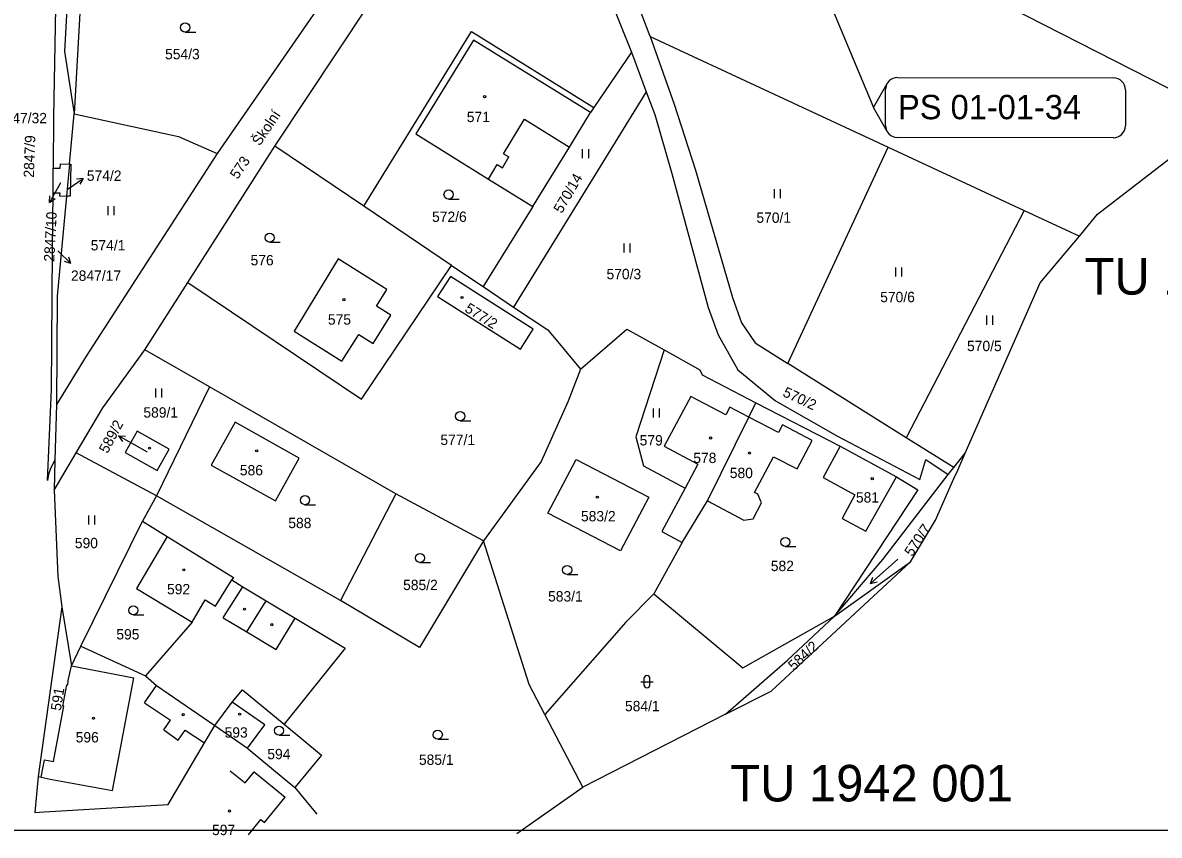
# Model space of a CAD drawing. Extents: x -558358 to -557517, y -1073785 to -1073189.
# Drawn here: x -558184.5 to -557998, y -1073784.9 to -1073651.5 of the extents above; entities that cross this region are included whole.
import ezdxf

# ---------------------------------------------------------------- set-up
doc = ezdxf.new("R2010")
doc.units = 0
for name, color, linetype in [('Hranice parcel', 7, 'Continuous'), ('Parcelní čísla', 7, 'Continuous'), ('Pop  PČ popisy', 7, 'Continuous'), ('Vnitřní kresba', 7, 'Continuous'), ('Vrstva 1', 7, 'Continuous'), ('Vrstva 2', 7, 'Continuous'), ('Vrstva 28', 7, 'Continuous'), ('Značky budov', 7, 'Continuous'), ('Značky kultur', 7, 'Continuous')]:
    doc.layers.add(name, color=color, linetype=linetype)

msp = doc.modelspace()

# ---------------------------------------------------------------- linework, layer by layer
at = {"layer": 'Hranice parcel'}
for p, q in [((-558126.57, -1073635.37), (-558152.59, -1073672.96)), ((-558047.53, -1073636.2), (-557987.38, -1073666.93)), ((-558083.83, -1073647.78), (-558081.75, -1073653.27)), ((-558081.75, -1073653.27), (-558081.56, -1073653.8)), ((-558081.56, -1073653.8), (-558042.48, -1073671.96)), ((-558084.61, -1073656.37), (-558090.78, -1073665.45)), ((-558084.61, -1073656.37), (-558082.19, -1073662.86)), ((-558082.19, -1073662.86), (-558103.95, -1073698.19)), ((-558082.19, -1073662.86), (-558080.79, -1073666.61)), ((-558090.78, -1073665.45), (-558091.34, -1073666.27)), ((-558176.83, -1073674.75), (-558176.05, -1073666.5)), ((-558008.13, -1073682.96), (-557987.38, -1073666.93)), ((-558157.39, -1073694.14), (-558143.16, -1073671.79)), ((-558128.54, -1073681.64), (-558143.16, -1073671.79)), ((-558058.98, -1073707.44), (-558042.48, -1073671.96)), ((-558042.48, -1073671.96), (-558020.18, -1073682.32)), ((-558178.3, -1073674.68), (-558176.83, -1073674.75)), ((-558176.83, -1073674.75), (-558177.33, -1073679.98)), ((-558176.83, -1073674.75), (-558176.6, -1073674.76)), ((-558176.6, -1073674.76), (-558176.71, -1073680)), ((-558179.54, -1073679.43), (-558179.49, -1073675.4)), ((-558178.45, -1073679.93), (-558177.33, -1073679.98)), ((-558176.71, -1073680), (-558177.33, -1073679.98)), ((-558114.13, -1073691.34), (-558128.54, -1073681.64)), ((-558100.81, -1073681.69), (-558108.93, -1073694.83)), ((-558020.18, -1073682.32), (-558039.55, -1073719.63)), ((-558020.18, -1073682.32), (-558011.11, -1073686.54)), ((-558011.11, -1073686.54), (-558008.13, -1073682.96)), ((-558017.53, -1073694.23), (-558011.11, -1073686.54)), ((-558114.13, -1073691.34), (-558108.93, -1073694.83)), ((-558164.46, -1073705.23), (-558157.39, -1073694.14)), ((-558108.93, -1073694.83), (-558103.95, -1073698.19)), ((-558029.85, -1073722.15), (-558017.53, -1073694.23)), ((-558153.86, -1073711.3), (-558164.46, -1073705.23)), ((-558079.26, -1073705.23), (-558083.89, -1073719.49)), ((-558039.55, -1073719.63), (-558058.98, -1073707.44)), ((-558153.86, -1073711.3), (-558162.58, -1073729.18)), ((-558123.29, -1073728.86), (-558153.86, -1073711.3)), ((-558178.98, -1073714.16), (-558179.23, -1073723.31)), ((-558065.38, -1073716.24), (-558064.19, -1073713.89)), ((-558064.19, -1073713.89), (-558050.38, -1073721.04)), ((-558072.16, -1073729.98), (-558065.38, -1073716.24)), ((-558083.89, -1073719.49), (-558082.62, -1073724.25)), ((-558031.72, -1073724.54), (-558039.55, -1073719.63)), ((-558050.38, -1073721.04), (-558041.12, -1073726.03)), ((-558179.37, -1073728.25), (-558175.74, -1073722.09)), ((-558179.23, -1073723.31), (-558179.37, -1073728.25)), ((-558162.58, -1073729.18), (-558175.74, -1073722.09)), ((-558031.72, -1073724.54), (-558029.85, -1073722.15)), ((-558082.62, -1073724.25), (-558075.83, -1073727.93)), ((-558032.62, -1073725.69), (-558031.72, -1073724.54)), ((-558162.58, -1073729.18), (-558164.87, -1073733.32)), ((-558132.34, -1073746.32), (-558162.58, -1073729.18)), ((-558123.29, -1073728.86), (-558132.34, -1073746.32)), ((-558108.92, -1073736.57), (-558123.29, -1073728.86)), ((-558076.28, -1073736.83), (-558072.16, -1073729.98)), ((-558174.95, -1073753.84), (-558164.87, -1073733.32)), ((-558164.87, -1073733.32), (-558160.79, -1073735.84)), ((-558076.28, -1073736.83), (-558080.95, -1073745.27)), ((-558061.7, -1073761.21), (-558038.85, -1073740)), ((-558051.32, -1073748.93), (-558043.37, -1073739.61)), ((-558051.32, -1073748.93), (-558038.85, -1073740)), ((-558080.95, -1073745.27), (-558085.52, -1073749.88)), ((-558178.08, -1073747.39), (-558181.97, -1073775.25)), ((-558178.08, -1073747.39), (-558176.52, -1073757.07)), ((-558058.99, -1073756.15), (-558051.32, -1073748.93)), ((-558085.52, -1073749.88), (-558098.82, -1073765.08)), ((-558176.52, -1073757.07), (-558174.95, -1073753.84)), ((-558174.95, -1073753.84), (-558164.36, -1073758.7)), ((-558069.16, -1073765.01), (-558058.99, -1073756.15)), ((-558069.16, -1073765.01), (-558061.7, -1073761.21)), ((-558152.96, -1073766.88), (-558150.14, -1073763.05)), ((-558092.62, -1073776.97), (-558098.82, -1073765.08)), ((-558069.16, -1073765.01), (-558092.62, -1073776.97)), ((-558152.96, -1073766.88), (-558147.64, -1073770.59)), ((-558147.64, -1073770.59), (-558147.54, -1073770.67)), ((-558147.54, -1073770.67), (-558139.85, -1073777.06)), ((-558181.97, -1073775.25), (-558182.51, -1073781.13)), ((-558139.85, -1073777.06), (-558136.25, -1073781.43)), ((-558103.4, -1073784.58), (-558092.62, -1073776.97)), ((-558182.51, -1073781.13), (-558181.01, -1073781.05))]:
    msp.add_line(p, q, dxfattribs=at)
for points in [[(-558086.19, -1073392.25), (-558100.56, -1073410.01), (-558117.51, -1073431.08), (-558131.78, -1073449.27), (-558138.48, -1073457.68), (-558143.38, -1073464.02), (-558146.99, -1073468.89), (-558150.46, -1073473.83), (-558152.02, -1073476.41), (-558154.26, -1073480.97), (-558156.46, -1073486.6), (-558158.91, -1073494.31), (-558160.3, -1073500.48), (-558162.16, -1073510.4), (-558165.76, -1073536.46), (-558169.94, -1073565.43), (-558173.74, -1073591.61), (-558177.66, -1073620.33), (-558178.51, -1073631.87), (-558179.02, -1073643), (-558179.24, -1073655.12), (-558179.45, -1073666.94), (-558179.49, -1073675.4)], [(-558175.82, -1073622.18), (-558177.63, -1073656.22), (-558176.05, -1073666.5)], [(-558175.82, -1073622.18), (-558174.18, -1073632.38), (-558176.05, -1073666.5)], [(-558143.16, -1073671.79), (-558122.68, -1073640.91), (-558116.74, -1073631.82), (-558110.18, -1073623.69)], [(-558110.18, -1073623.69), (-558095.16, -1073631.27), (-558088.2, -1073647.35), (-558084.61, -1073656.37)], [(-558128.54, -1073681.64), (-558110.84, -1073652.98), (-558090.78, -1073665.45)], [(-558091.34, -1073666.27), (-558110.52, -1073654.36), (-558120.01, -1073669.73), (-558108.1, -1073677.21), (-558100.81, -1073681.69)], [(-558081.56, -1073653.8), (-558077.6, -1073664.88), (-558074.09, -1073675.7), (-558068.03, -1073696.59), (-558066.56, -1073700.76), (-558064.34, -1073704.08), (-558058.98, -1073707.44)], [(-558176.05, -1073666.5), (-558158.95, -1073670.2), (-558152.59, -1073672.96)], [(-558100.81, -1073681.69), (-558094.8, -1073671.95), (-558091.34, -1073666.27)], [(-558080.79, -1073666.61), (-558077.98, -1073676.29), (-558072.03, -1073698.27), (-558070.37, -1073702.74), (-558067.15, -1073708.5), (-558060.97, -1073713.55), (-558050.8, -1073719.38), (-558037.27, -1073726.47), (-558036.33, -1073723.21), (-558032.62, -1073725.69)], [(-558152.59, -1073672.96), (-558174.12, -1073706.25), (-558178.98, -1073714.16)], [(-558179.49, -1073675.4), (-558178.35, -1073675.4), (-558178.3, -1073674.68)], [(-558180.47, -1073726.64), (-558179.79, -1073711.73), (-558179.61, -1073688.81), (-558179.54, -1073679.43)], [(-558179.54, -1073679.43), (-558178.44, -1073679.44), (-558178.45, -1073679.93)], [(-558177.33, -1073679.98), (-558178.88, -1073696.38), (-558178.98, -1073714.16)], [(-558157.39, -1073694.14), (-558128.92, -1073713.32), (-558114.13, -1073691.34)], [(-558124.75, -1073695.3), (-558132.74, -1073690.28), (-558139.98, -1073702.13), (-558132.13, -1073707.05), (-558129.35, -1073702.69), (-558127, -1073704.15), (-558124.1, -1073699.49), (-558126.45, -1073698.03), (-558124.75, -1073695.3)], [(-558114.32, -1073693.16), (-558116.42, -1073696.46), (-558102.81, -1073705.11), (-558100.72, -1073701.82), (-558114.32, -1073693.16)], [(-558103.95, -1073698.19), (-558098.36, -1073701.95), (-558092.97, -1073708.36)], [(-558092.97, -1073708.36), (-558085.4, -1073701.82), (-558079.26, -1073705.23)], [(-558175.74, -1073722.09), (-558171.39, -1073714.72), (-558164.46, -1073705.23)], [(-558079.26, -1073705.23), (-558073.37, -1073708.51), (-558073.01, -1073709.33), (-558064.19, -1073713.89)], [(-558092.97, -1073708.36), (-558095.02, -1073713.61), (-558099.46, -1073723.54), (-558108.92, -1073736.57)], [(-558065.38, -1073716.24), (-558068.48, -1073714.62), (-558069.13, -1073715.86), (-558074.89, -1073712.87), (-558079.25, -1073721.04), (-558073.73, -1073723.99), (-558075.83, -1073727.93)], [(-558072.16, -1073729.98), (-558066.15, -1073733.15), (-558064.66, -1073732.92), (-558063.26, -1073730.33), (-558063.88, -1073728.9), (-558064.4, -1073728.63), (-558061.31, -1073722.78), (-558057.44, -1073724.76), (-558054.98, -1073720.06), (-558059.84, -1073717.49), (-558060.51, -1073718.77), (-558065.38, -1073716.24)], [(-558139.17, -1073722.99), (-558149.67, -1073717.07), (-558153.56, -1073724.14), (-558143.05, -1073729.97), (-558139.17, -1073722.99)], [(-558160.49, -1073721.53), (-558165.71, -1073718.57), (-558167.69, -1073722.06), (-558162.47, -1073725.03), (-558160.49, -1073721.53)], [(-558050.38, -1073721.04), (-558053.17, -1073726.18), (-558047.96, -1073729.01), (-558050.05, -1073732.86), (-558046.14, -1073734.98), (-558041.12, -1073726.03)], [(-558179.23, -1073723.31), (-558179.97, -1073724.66), (-558180.29, -1073725.65), (-558180.47, -1073726.64)], [(-558081.79, -1073729.39), (-558086.39, -1073738.22), (-558098.32, -1073732.01), (-558093.7, -1073723.21), (-558081.79, -1073729.39)], [(-558031.69, -1073726.31), (-558031.08, -1073724.94), (-558029.85, -1073722.15)], [(-558041.12, -1073726.03), (-558037.61, -1073728.19), (-558051.32, -1073748.93)], [(-558043.37, -1073739.61), (-558035.2, -1073729), (-558032.62, -1073725.69)], [(-558038.85, -1073740), (-558034.7, -1073733.14), (-558031.69, -1073726.31)], [(-558179.37, -1073728.25), (-558178.74, -1073742.4), (-558178.08, -1073747.39)], [(-558075.83, -1073727.93), (-558079.61, -1073735.04), (-558076.28, -1073736.83)], [(-558160.79, -1073735.84), (-558165.86, -1073744.39), (-558156.72, -1073749.9), (-558164.36, -1073758.7)], [(-558160.79, -1073735.84), (-558149.94, -1073742.55), (-558150.18, -1073742.93), (-558148.38, -1073744.09), (-558144.55, -1073746.39), (-558139.78, -1073749.25), (-558131.58, -1073754.18), (-558141.63, -1073766.63)], [(-558108.92, -1073736.57), (-558119.39, -1073754.05), (-558132.34, -1073746.32)], [(-558098.82, -1073765.08), (-558101.41, -1073760.13), (-558108.92, -1073736.57)], [(-558080.95, -1073745.27), (-558066.32, -1073757.38), (-558051.32, -1073748.93)], [(-558181.97, -1073775.25), (-558181.48, -1073775.34), (-558180.95, -1073772.5), (-558179.48, -1073772.78), (-558177.77, -1073763.68), (-558177.92, -1073763.66), (-558177.27, -1073760.18), (-558177.12, -1073760.21), (-558177.05, -1073759.47), (-558176.52, -1073757.07)], [(-558164.36, -1073758.7), (-558162.58, -1073760.28), (-558152.96, -1073766.88)], [(-558150.14, -1073763.05), (-558148.43, -1073760.98), (-558141.63, -1073766.63)], [(-558147.64, -1073770.59), (-558144.77, -1073766.75), (-558150.14, -1073763.05)], [(-558181.01, -1073781.05), (-558160.65, -1073779.83), (-558154.69, -1073769.71), (-558152.96, -1073766.88)], [(-558141.63, -1073766.63), (-558135.48, -1073771.74), (-558139.85, -1073777.06)]]:
    msp.add_lwpolyline(points, dxfattribs=at)
at = {"layer": 'Pop  PČ popisy'}
for p, q in [((-558177.05, -1073678.78), (-558174.59, -1073677.06)), ((-558174.59, -1073677.06), (-558175.7, -1073677.22)), ((-558174.59, -1073677.06), (-558175.12, -1073678.04)), ((-558178.66, -1073678.4), (-558180.11, -1073681.02)), ((-558178.32, -1073677.78), (-558178.66, -1073678.4)), ((-558180.11, -1073681.02), (-558180.07, -1073679.91)), ((-558180.11, -1073681.02), (-558179.19, -1073680.39)), ((-558178.75, -1073688.95), (-558176.59, -1073691.03)), ((-558176.59, -1073691.03), (-558176.96, -1073689.98)), ((-558176.59, -1073691.03), (-558177.66, -1073690.7)), ((-558166.16, -1073720.8), (-558168.79, -1073719.34)), ((-558168.79, -1073719.34), (-558167.67, -1073719.39)), ((-558168.79, -1073719.34), (-558168.15, -1073720.27)), ((-558164.05, -1073721.99), (-558166.16, -1073720.8))]:
    msp.add_line(p, q, dxfattribs=at)
at = {"layer": 'Vnitřní kresba'}
for p, q in [((-558105.6, -1073673.04), (-558102.19, -1073667.36)), ((-558102.19, -1073667.36), (-558094.8, -1073671.95)), ((-558105.6, -1073673.04), (-558104.74, -1073673.55)), ((-558108.1, -1073677.21), (-558106.65, -1073674.8)), ((-558106.65, -1073674.8), (-558105.79, -1073675.32)), ((-558105.79, -1073675.32), (-558104.74, -1073673.55)), ((-558152.86, -1073747.27), (-558150.18, -1073742.93)), ((-558151.46, -1073748.94), (-558148.38, -1073744.09)), ((-558156.72, -1073749.9), (-558154.56, -1073746.22)), ((-558154.56, -1073746.22), (-558152.86, -1073747.27)), ((-558147.74, -1073751.5), (-558144.55, -1073746.39)), ((-558151.61, -1073749.2), (-558151.46, -1073748.94)), ((-558151.61, -1073749.2), (-558147.74, -1073751.5)), ((-558142.92, -1073754.36), (-558139.78, -1073749.25)), ((-558147.74, -1073751.5), (-558142.92, -1073754.36)), ((-558176.52, -1073757.07), (-558166.27, -1073759.01)), ((-558169.76, -1073777.52), (-558166.27, -1073759.01)), ((-558164.5, -1073763.14), (-558162.58, -1073760.28)), ((-558164.5, -1073763.14), (-558160.25, -1073766.01)), ((-558161.38, -1073767.55), (-558160.25, -1073766.01)), ((-558161.38, -1073767.55), (-558158.98, -1073769.26)), ((-558158.98, -1073769.26), (-558157.87, -1073767.62)), ((-558157.87, -1073767.62), (-558154.69, -1073769.71)), ((-558181.48, -1073775.34), (-558180, -1073775.65)), ((-558180, -1073775.65), (-558169.76, -1073777.52)), ((-558150.48, -1073774.29), (-558148.03, -1073776.28)), ((-558148.03, -1073776.28), (-558146.55, -1073774.45)), ((-558146.55, -1073774.45), (-558141.43, -1073778.61)), ((-558144.83, -1073782.8), (-558141.43, -1073778.61)), ((-558147.47, -1073784.78), (-558145.45, -1073782.3)), ((-558145.45, -1073782.3), (-558144.83, -1073782.8))]:
    msp.add_line(p, q, dxfattribs=at)
at = {"layer": 'Vrstva 1'}
msp.add_line((-557516.53, -1073784.09), (-558357.53, -1073784.09), dxfattribs=at)
at = {"layer": 'Vrstva 28'}
for p, q in [((-558150.16, -1073413.05), (-558044.9, -1073665.43)), ((-558044.9, -1073665.43), (-558042.67, -1073661.51)), ((-558040.96, -1073660.51), (-558005.53, -1073660.57)), ((-558042.94, -1073668.38), (-558042.93, -1073662.48)), ((-558003.56, -1073662.54), (-558003.57, -1073668.45)), ((-558042.68, -1073669.35), (-558044.9, -1073665.43)), ((-558005.54, -1073670.41), (-558040.97, -1073670.36))]:
    msp.add_line(p, q, dxfattribs=at)
for centre, start, end in [((-558040.96, -1073662.48), 89.9095, 179.9095), ((-558005.53, -1073662.54), 359.9095, 89.9095), ((-558040.97, -1073668.39), 179.9095, 269.9095), ((-558005.54, -1073668.44), 269.9095, 359.9095)]:
    msp.add_arc(centre, 1.97, start, end, dxfattribs=at)
at = {"layer": 'Značky budov'}
for centre in [(-558108.71, -1073663.65), (-558131.8, -1073696.98), (-558112.42, -1073696.62), (-558071.63, -1073719.68), (-558163.71, -1073721.34), (-558146.11, -1073721.79), (-558065.25, -1073722.15), (-558045.1, -1073726.35), (-558090.22, -1073729.39), (-558158.06, -1073741.3), (-558148.12, -1073747.76), (-558143.62, -1073750.31), (-558172.89, -1073765.67), (-558158.17, -1073765.09), (-558148.92, -1073764.99), (-558150.58, -1073780.89)]:
    msp.add_circle(centre, 0.175, dxfattribs=at)
at = {"layer": 'Značky kultur'}
for p, q in [((-558157.86, -1073653.06), (-558156.11, -1073653.06)), ((-558092.63, -1073673.76), (-558092.63, -1073672.26)), ((-558091.63, -1073673.76), (-558091.63, -1073672.26)), ((-558061.16, -1073680.32), (-558061.16, -1073678.82)), ((-558060.16, -1073680.32), (-558060.16, -1073678.82)), ((-558114.63, -1073680.46), (-558112.88, -1073680.46)), ((-558170.5, -1073683.13), (-558170.5, -1073681.63)), ((-558169.5, -1073683.13), (-558169.5, -1073681.63)), ((-558144, -1073687.55), (-558142.25, -1073687.55)), ((-558085.83, -1073689.23), (-558085.83, -1073687.73)), ((-558084.83, -1073689.23), (-558084.83, -1073687.73)), ((-558041.24, -1073693.17), (-558041.24, -1073691.67)), ((-558040.24, -1073693.17), (-558040.24, -1073691.67)), ((-558026.3, -1073701.09), (-558026.3, -1073699.59)), ((-558025.3, -1073701.09), (-558025.3, -1073699.59)), ((-558162.67, -1073713.05), (-558162.67, -1073711.55)), ((-558161.67, -1073713.05), (-558161.67, -1073711.55)), ((-558080.99, -1073716.31), (-558080.99, -1073714.81)), ((-558079.99, -1073716.31), (-558079.99, -1073714.81)), ((-558112.73, -1073716.84), (-558110.98, -1073716.84)), ((-558138.2, -1073730.62), (-558136.45, -1073730.62)), ((-558173.68, -1073733.89), (-558173.68, -1073732.39)), ((-558172.68, -1073733.89), (-558172.68, -1073732.39)), ((-558059.37, -1073737.48), (-558057.62, -1073737.48)), ((-558119.32, -1073740.13), (-558117.57, -1073740.13)), ((-558040.91, -1073739.54), (-558045.37, -1073743.55)), ((-558095.17, -1073742.09), (-558093.42, -1073742.09)), ((-558045.37, -1073743.55), (-558044.98, -1073742.53)), ((-558045.37, -1073743.55), (-558044.31, -1073743.27)), ((-558166.36, -1073748.71), (-558164.61, -1073748.71)), ((-558083.08, -1073759.67), (-558081.08, -1073759.67)), ((-558082.58, -1073759.17), (-558082.58, -1073760.17)), ((-558081.58, -1073760.17), (-558081.58, -1073759.17)), ((-558142.44, -1073768.45), (-558140.69, -1073768.45)), ((-558116.4, -1073769.12), (-558114.65, -1073769.12))]:
    msp.add_line(p, q, dxfattribs=at)
for centre in [(-558157.86, -1073652.31), (-558114.63, -1073679.71), (-558144, -1073686.8), (-558112.73, -1073716.09), (-558138.2, -1073729.87), (-558059.37, -1073736.73), (-558119.32, -1073739.38), (-558095.17, -1073741.34), (-558166.36, -1073747.96), (-558142.44, -1073767.7), (-558116.4, -1073768.37)]:
    msp.add_circle(centre, 0.75, dxfattribs=at)
for centre, start, end in [((-558082.08, -1073759.17), 0, 180), ((-558082.08, -1073760.17), 180, 359.9879)]:
    msp.add_arc(centre, 0.5, start, end, dxfattribs=at)

# ---------------------------------------------------------------- texts
at = {"layer": 'Parcelní čísla'}
for s, p in [('554/3', (-558161.15, -1073657.52)), ('2847/32', (-558188.75, -1073668.02)), ('571', (-558111.64, -1073667.83)), ('574/2', (-558173.99, -1073677.47)), ('572/6', (-558117.34, -1073684.21)), ('570/1', (-558064.11, -1073684.36)), ('574/1', (-558173.35, -1073688.89)), ('576', (-558147.12, -1073691.34)), ('570/3', (-558088.71, -1073693.62)), ('2847/17', (-558176.59, -1073693.88)), ('570/6', (-558043.8, -1073697.39)), ('575', (-558134.43, -1073701.08)), ('570/5', (-558029.55, -1073705.42)), ('589/1', (-558164.71, -1073716.33)), ('577/1', (-558115.97, -1073720.83)), ('579', (-558083.27, -1073720.9)), ('578', (-558074.47, -1073723.79)), ('586', (-558148.88, -1073725.81)), ('580', (-558068.48, -1073726.26)), ('581', (-558047.78, -1073730.27)), ('588', (-558140.93, -1073734.47)), ('583/2', (-558092.9, -1073733.36)), ('590', (-558175.96, -1073737.76)), ('582', (-558061.75, -1073741.52)), ('592', (-558160.83, -1073745.33)), ('585/2', (-558122.09, -1073744.64)), ('583/1', (-558098.3, -1073746.51)), ('595', (-558169.15, -1073752.74)), ('584/1', (-558085.68, -1073764.52)), ('596', (-558175.82, -1073769.64)), ('593', (-558151.38, -1073768.85)), ('594', (-558144.37, -1073772.39)), ('585/1', (-558119.49, -1073773.32)), ('597', (-558153.44, -1073784.85))]:
    msp.add_text(s, height=1.7, dxfattribs=at).set_placement(p)
for s, rotation, p in [('2847/9', 88, (-558182.68, -1073676.97)), ('573', 56, (-558149.24, -1073677.32)), ('570/14', 60, (-558096.05, -1073682.93)), ('2847/10', 87, (-558179.35, -1073690.79)), ('577/2', 328, (-558112.11, -1073698.84)), ('570/2', 335, (-558059.92, -1073712.75)), ('589/2', 62, (-558170.6, -1073722.33)), ('570/7', 56, (-558038.56, -1073739.25)), ('584/2', 43, (-558057.95, -1073757.95)), ('591', 81, (-558178.26, -1073764.52))]:
    msp.add_text(s, height=1.7, rotation=rotation, dxfattribs=at).set_placement(p)
at = {"layer": 'Pop  PČ popisy'}
msp.add_text('Školní', height=1.7, rotation=56, dxfattribs=at).set_placement((-558145.62, -1073671.85))
at = {"layer": 'Vrstva 2'}
for s, p in [('TU 1942 002', (-558010.26, -1073696.15)), ('TU 1942 001', (-558068.41, -1073779.32))]:
    msp.add_text(s, height=6, dxfattribs=at).set_placement(p)
at = {"layer": 'Vrstva 28'}
msp.add_text('PS 01-01-34', height=4, dxfattribs=at).set_placement((-558040.87, -1073667.36))

doc.saveas('drawing.dxf')
